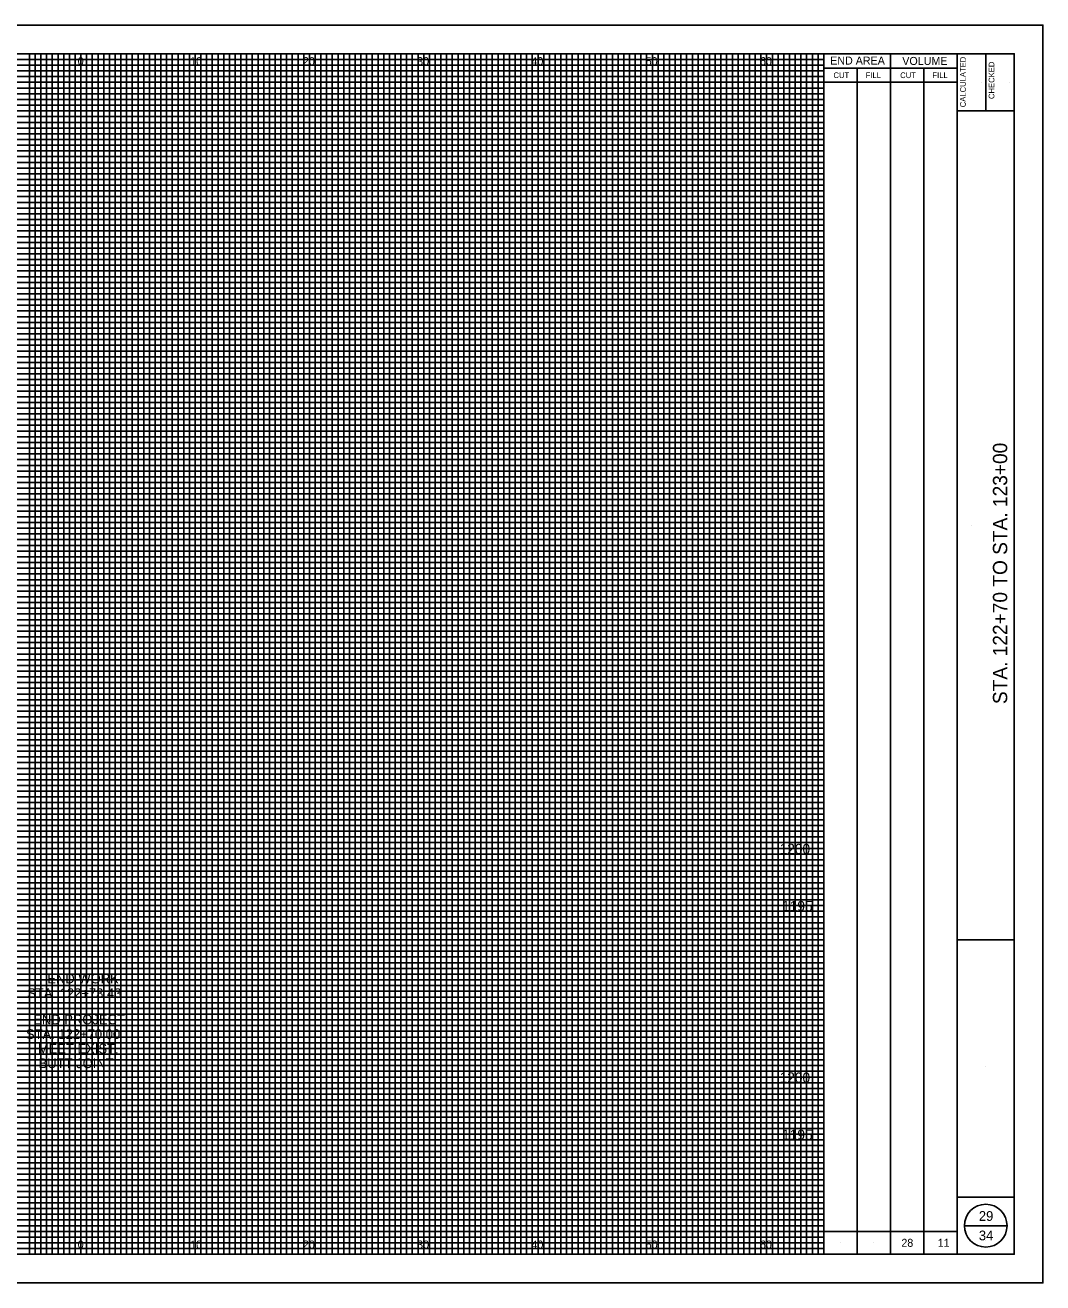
# Model space of a CAD drawing. Extents: x -10 to 160, y -13 to 1488.
# Drawn here: x 71 to 160, y 1377.5 to 1487.5 of the extents above; entities that cross this region are included whole.
import ezdxf

# ---------------------------------------------------------------- set-up
doc = ezdxf.new("R2010")
doc.units = 0
for name, color, linetype in [('DR_X_Storm_Sewer', 7, 'Continuous'), ('GK_Cells', 7, 'Continuous'), ('GK_Visualization', 7, 'Continuous'), ('PF_P_Sta_Elev_Text', 7, 'Continuous'), ('PF_X_Ground_Line', 7, 'Continuous'), ('PV_P_EOP', 7, 'Continuous'), ('PV_P_Shoulder', 7, 'Continuous')]:
    doc.layers.add(name, color=color, linetype=linetype)

msp = doc.modelspace()

# ---------------------------------------------------------------- linework, layer by layer
at = {"layer": 'GK_Cells'}
for p, q in [((152.5, 1380), (152.5, 1485)), ((155, 1485), (155, 1480)), ((152.5, 1480), (157.5, 1480)), ((152.5, 1407.5), (157.5, 1407.5)), ((152.5, 1385), (157.5, 1385))]:
    msp.add_line(p, q, dxfattribs=at)
msp.add_lwpolyline([(0, 1485), (157.5, 1485), (157.5, 1380), (0, 1380)], close=True, dxfattribs=at)
at = {"layer": 'PF_P_Sta_Elev_Text'}
msp.add_lwpolyline([(-10, 1377.5), (160, 1377.5), (160, 1487.5), (-10, 1487.5)], close=True, dxfattribs=at)
at = {"layer": 'PF_X_Ground_Line'}
for p, q in [((140.83, 1380), (140.83, 1485)), ((146.67, 1380), (146.67, 1485)), ((140.83, 1483.75), (152.5, 1483.75)), ((143.75, 1380), (143.75, 1483.75)), ((149.58, 1380), (149.58, 1483.75)), ((140.83, 1482.5), (152.5, 1482.5)), ((154.6, 1482.52), (154.6, 1482.52)), ((157.1, 1482.52), (157.1, 1482.52)), ((153.75, 1443.75), (153.75, 1443.75)), ((156.26, 1443.75), (156.26, 1443.75)), ((155, 1396.46), (155, 1396.46)), ((155, 1382.92), (155, 1382.92)), ((140.83, 1382), (152.5, 1382)), ((153.12, 1382.5), (156.88, 1382.5)), ((142.29, 1381), (142.29, 1381)), ((145.21, 1381), (145.21, 1381)), ((148.12, 1381), (148.12, 1381)), ((151.04, 1381), (151.04, 1381)), ((155, 1381.22), (155, 1381.22))]:
    msp.add_line(p, q, dxfattribs=at)
msp.add_circle((155, 1382.5), 1.87, dxfattribs=at)
at = {"layer": 'PV_P_EOP'}
for p, q in [((71.33, 1380), (71.33, 1485)), ((71.83, 1380), (71.83, 1485)), ((72.33, 1380), (72.33, 1485)), ((72.83, 1380), (72.83, 1485)), ((73.33, 1380), (73.33, 1485)), ((73.83, 1380), (73.83, 1485)), ((74.33, 1380), (74.33, 1485)), ((74.83, 1380), (74.83, 1485)), ((75.33, 1380), (75.33, 1485)), ((76.33, 1380), (76.33, 1485)), ((76.83, 1380), (76.83, 1485)), ((77.33, 1380), (77.33, 1485)), ((77.83, 1380), (77.83, 1485)), ((78.33, 1380), (78.33, 1485)), ((78.83, 1380), (78.83, 1485)), ((79.33, 1380), (79.33, 1485)), ((79.83, 1380), (79.83, 1485)), ((80.33, 1380), (80.33, 1485)), ((81.33, 1380), (81.33, 1485)), ((81.83, 1380), (81.83, 1485)), ((82.33, 1380), (82.33, 1485)), ((82.83, 1380), (82.83, 1485)), ((83.33, 1380), (83.33, 1485)), ((83.83, 1380), (83.83, 1485)), ((84.33, 1380), (84.33, 1485)), ((84.83, 1380), (84.83, 1485)), ((85.33, 1380), (85.33, 1485)), ((86.33, 1380), (86.33, 1485)), ((86.83, 1380), (86.83, 1485)), ((87.33, 1380), (87.33, 1485)), ((87.83, 1380), (87.83, 1485)), ((88.33, 1380), (88.33, 1485)), ((88.83, 1380), (88.83, 1485)), ((89.33, 1380), (89.33, 1485)), ((89.83, 1380), (89.83, 1485)), ((90.33, 1380), (90.33, 1485)), ((91.33, 1380), (91.33, 1485)), ((91.83, 1380), (91.83, 1485)), ((92.33, 1380), (92.33, 1485)), ((92.83, 1380), (92.83, 1485)), ((93.33, 1380), (93.33, 1485)), ((93.83, 1380), (93.83, 1485)), ((94.33, 1380), (94.33, 1485)), ((94.83, 1380), (94.83, 1485)), ((95.33, 1380), (95.33, 1485)), ((96.33, 1380), (96.33, 1485)), ((96.83, 1380), (96.83, 1485)), ((97.33, 1380), (97.33, 1485)), ((97.83, 1380), (97.83, 1485)), ((98.33, 1380), (98.33, 1485)), ((98.83, 1380), (98.83, 1485)), ((99.33, 1380), (99.33, 1485)), ((99.83, 1380), (99.83, 1485)), ((100.33, 1380), (100.33, 1485)), ((101.33, 1380), (101.33, 1485)), ((101.83, 1380), (101.83, 1485)), ((102.33, 1380), (102.33, 1485)), ((102.83, 1380), (102.83, 1485)), ((103.33, 1380), (103.33, 1485)), ((103.83, 1380), (103.83, 1485)), ((104.33, 1380), (104.33, 1485)), ((104.83, 1380), (104.83, 1485)), ((105.33, 1380), (105.33, 1485)), ((106.33, 1380), (106.33, 1485)), ((106.83, 1380), (106.83, 1485)), ((107.33, 1380), (107.33, 1485)), ((107.83, 1380), (107.83, 1485)), ((108.33, 1380), (108.33, 1485)), ((108.83, 1380), (108.83, 1485)), ((109.33, 1380), (109.33, 1485)), ((109.83, 1380), (109.83, 1485)), ((110.33, 1380), (110.33, 1485)), ((111.33, 1380), (111.33, 1485)), ((111.83, 1380), (111.83, 1485)), ((112.33, 1380), (112.33, 1485)), ((112.83, 1380), (112.83, 1485)), ((113.33, 1380), (113.33, 1485)), ((113.83, 1380), (113.83, 1485)), ((114.33, 1380), (114.33, 1485)), ((114.83, 1380), (114.83, 1485)), ((115.33, 1380), (115.33, 1485)), ((116.33, 1380), (116.33, 1485)), ((116.83, 1380), (116.83, 1485)), ((117.33, 1380), (117.33, 1485)), ((117.83, 1380), (117.83, 1485)), ((118.33, 1380), (118.33, 1485)), ((118.83, 1380), (118.83, 1485)), ((119.33, 1380), (119.33, 1485)), ((119.83, 1380), (119.83, 1485)), ((120.33, 1380), (120.33, 1485)), ((121.33, 1380), (121.33, 1485)), ((121.83, 1380), (121.83, 1485)), ((122.33, 1380), (122.33, 1485)), ((122.83, 1380), (122.83, 1485)), ((123.33, 1380), (123.33, 1485)), ((123.83, 1380), (123.83, 1485)), ((124.33, 1380), (124.33, 1485)), ((124.83, 1380), (124.83, 1485)), ((125.33, 1380), (125.33, 1485)), ((126.33, 1380), (126.33, 1485)), ((126.83, 1380), (126.83, 1485)), ((127.33, 1380), (127.33, 1485)), ((127.83, 1380), (127.83, 1485)), ((128.33, 1380), (128.33, 1485)), ((128.83, 1380), (128.83, 1485)), ((129.33, 1380), (129.33, 1485)), ((129.83, 1380), (129.83, 1485)), ((130.33, 1380), (130.33, 1485)), ((131.33, 1380), (131.33, 1485)), ((131.83, 1380), (131.83, 1485)), ((132.33, 1380), (132.33, 1485)), ((132.83, 1380), (132.83, 1485)), ((133.33, 1380), (133.33, 1485)), ((133.83, 1380), (133.83, 1485)), ((134.33, 1380), (134.33, 1485)), ((134.83, 1380), (134.83, 1485)), ((135.33, 1380), (135.33, 1485)), ((136.33, 1380), (136.33, 1485)), ((136.83, 1380), (136.83, 1485)), ((137.33, 1380), (137.33, 1485)), ((137.83, 1380), (137.83, 1485)), ((138.33, 1380), (138.33, 1485)), ((138.83, 1380), (138.83, 1485)), ((139.33, 1380), (139.33, 1485)), ((139.83, 1380), (139.83, 1485)), ((140.33, 1380), (140.33, 1485)), ((5.83, 1484.5), (140.83, 1484.5)), ((5.83, 1484), (140.83, 1484)), ((5.83, 1483.5), (140.83, 1483.5)), ((5.83, 1483), (140.83, 1483)), ((5.83, 1482.5), (140.83, 1482.5)), ((5.83, 1482), (140.83, 1482)), ((5.83, 1481.5), (140.83, 1481.5)), ((5.83, 1481), (140.83, 1481)), ((5.83, 1480.5), (140.83, 1480.5)), ((5.83, 1479.5), (140.83, 1479.5)), ((5.83, 1479), (140.83, 1479)), ((5.83, 1478.5), (140.83, 1478.5)), ((5.83, 1478), (140.83, 1478)), ((5.83, 1477.5), (140.83, 1477.5)), ((5.83, 1477), (140.83, 1477)), ((5.83, 1476.5), (140.83, 1476.5)), ((5.83, 1476), (140.83, 1476)), ((5.83, 1475.5), (140.83, 1475.5)), ((5.83, 1474.5), (140.83, 1474.5)), ((5.83, 1474), (140.83, 1474)), ((5.83, 1473.5), (140.83, 1473.5)), ((5.83, 1473), (140.83, 1473)), ((5.83, 1472.5), (140.83, 1472.5)), ((5.83, 1472), (140.83, 1472)), ((5.83, 1471.5), (140.83, 1471.5)), ((5.83, 1471), (140.83, 1471)), ((5.83, 1470.5), (140.83, 1470.5)), ((5.83, 1469.5), (140.83, 1469.5)), ((5.83, 1469), (140.83, 1469)), ((5.83, 1468.5), (140.83, 1468.5)), ((5.83, 1468), (140.83, 1468)), ((5.83, 1467.5), (140.83, 1467.5)), ((5.83, 1467), (140.83, 1467)), ((5.83, 1466.5), (140.83, 1466.5)), ((5.83, 1466), (140.83, 1466)), ((5.83, 1465.5), (140.83, 1465.5)), ((5.83, 1464.5), (140.83, 1464.5)), ((5.83, 1464), (140.83, 1464)), ((5.83, 1463.5), (140.83, 1463.5)), ((5.83, 1463), (140.83, 1463)), ((5.83, 1462.5), (140.83, 1462.5)), ((5.83, 1462), (140.83, 1462)), ((5.83, 1461.5), (140.83, 1461.5)), ((5.83, 1461), (140.83, 1461)), ((5.83, 1460.5), (140.83, 1460.5)), ((5.83, 1459.5), (140.83, 1459.5)), ((5.83, 1459), (140.83, 1459)), ((5.83, 1458.5), (140.83, 1458.5)), ((5.83, 1458), (140.83, 1458)), ((5.83, 1457.5), (140.83, 1457.5)), ((5.83, 1457), (140.83, 1457)), ((5.83, 1456.5), (140.83, 1456.5)), ((5.83, 1456), (140.83, 1456)), ((5.83, 1455.5), (140.83, 1455.5)), ((5.83, 1454.5), (140.83, 1454.5)), ((5.83, 1454), (140.83, 1454)), ((5.83, 1453.5), (140.83, 1453.5)), ((5.83, 1453), (140.83, 1453)), ((5.83, 1452.5), (140.83, 1452.5)), ((5.83, 1452), (140.83, 1452)), ((5.83, 1451.5), (140.83, 1451.5)), ((5.83, 1451), (140.83, 1451)), ((5.83, 1450.5), (140.83, 1450.5)), ((5.83, 1449.5), (140.83, 1449.5)), ((5.83, 1449), (140.83, 1449)), ((5.83, 1448.5), (140.83, 1448.5)), ((5.83, 1448), (140.83, 1448)), ((5.83, 1447.5), (140.83, 1447.5)), ((5.83, 1447), (140.83, 1447)), ((5.83, 1446.5), (140.83, 1446.5)), ((5.83, 1446), (140.83, 1446)), ((5.83, 1445.5), (140.83, 1445.5)), ((5.83, 1444.5), (140.83, 1444.5)), ((5.83, 1444), (140.83, 1444)), ((5.83, 1443.5), (140.83, 1443.5)), ((5.83, 1443), (140.83, 1443)), ((5.83, 1442.5), (140.83, 1442.5)), ((5.83, 1442), (140.83, 1442)), ((5.83, 1441.5), (140.83, 1441.5)), ((5.83, 1441), (140.83, 1441)), ((5.83, 1440.5), (140.83, 1440.5)), ((5.83, 1439.5), (140.83, 1439.5)), ((5.83, 1439), (140.83, 1439)), ((5.83, 1438.5), (140.83, 1438.5)), ((5.83, 1438), (140.83, 1438)), ((5.83, 1437.5), (140.83, 1437.5)), ((5.83, 1437), (140.83, 1437)), ((5.83, 1436.5), (140.83, 1436.5)), ((5.83, 1436), (140.83, 1436)), ((5.83, 1435.5), (140.83, 1435.5)), ((5.83, 1434.5), (140.83, 1434.5)), ((5.83, 1434), (140.83, 1434)), ((5.83, 1433.5), (140.83, 1433.5)), ((5.83, 1433), (140.83, 1433)), ((5.83, 1432.5), (140.83, 1432.5)), ((5.83, 1432), (140.83, 1432)), ((5.83, 1431.5), (140.83, 1431.5)), ((5.83, 1431), (140.83, 1431)), ((5.83, 1430.5), (140.83, 1430.5)), ((5.83, 1429.5), (140.83, 1429.5)), ((5.83, 1429), (140.83, 1429)), ((5.83, 1428.5), (140.83, 1428.5)), ((5.83, 1428), (140.83, 1428)), ((5.83, 1427.5), (140.83, 1427.5)), ((5.83, 1427), (140.83, 1427)), ((5.83, 1426.5), (140.83, 1426.5)), ((5.83, 1426), (140.83, 1426)), ((5.83, 1425.5), (140.83, 1425.5)), ((5.83, 1424.5), (140.83, 1424.5)), ((5.83, 1424), (140.83, 1424)), ((5.83, 1423.5), (140.83, 1423.5)), ((5.83, 1423), (140.83, 1423)), ((5.83, 1422.5), (140.83, 1422.5)), ((5.83, 1422), (140.83, 1422)), ((5.83, 1421.5), (140.83, 1421.5)), ((5.83, 1421), (140.83, 1421)), ((5.83, 1420.5), (140.83, 1420.5)), ((5.83, 1419.5), (140.83, 1419.5)), ((5.83, 1419), (140.83, 1419)), ((5.83, 1418.5), (140.83, 1418.5)), ((5.83, 1418), (140.83, 1418)), ((5.83, 1417.5), (140.83, 1417.5)), ((5.83, 1417), (140.83, 1417)), ((5.83, 1416.5), (140.83, 1416.5)), ((5.83, 1416), (140.83, 1416)), ((5.83, 1415.5), (140.83, 1415.5)), ((5.83, 1414.5), (140.83, 1414.5)), ((5.83, 1414), (140.83, 1414)), ((5.83, 1413.5), (140.83, 1413.5)), ((5.83, 1413), (140.83, 1413)), ((5.83, 1412.5), (140.83, 1412.5)), ((5.83, 1412), (140.83, 1412)), ((5.83, 1411.5), (140.83, 1411.5)), ((5.83, 1411), (140.83, 1411)), ((5.83, 1410.5), (140.83, 1410.5)), ((5.83, 1409.5), (140.83, 1409.5)), ((5.83, 1409), (140.83, 1409)), ((5.83, 1408.5), (140.83, 1408.5)), ((5.83, 1408), (140.83, 1408)), ((5.83, 1407.5), (140.83, 1407.5)), ((5.83, 1407), (140.83, 1407)), ((5.83, 1406.5), (140.83, 1406.5)), ((5.83, 1406), (140.83, 1406)), ((5.83, 1405.5), (140.83, 1405.5)), ((5.83, 1404.5), (140.83, 1404.5)), ((5.83, 1404), (140.83, 1404)), ((5.83, 1403.5), (140.83, 1403.5)), ((5.83, 1403), (140.83, 1403)), ((5.83, 1402.5), (140.83, 1402.5)), ((5.83, 1402), (140.83, 1402)), ((5.83, 1401.5), (140.83, 1401.5)), ((5.83, 1401), (140.83, 1401)), ((5.83, 1400.5), (140.83, 1400.5)), ((5.83, 1399.5), (140.83, 1399.5)), ((5.83, 1399), (140.83, 1399)), ((5.83, 1398.5), (140.83, 1398.5)), ((5.83, 1398), (140.83, 1398)), ((5.83, 1397.5), (140.83, 1397.5)), ((5.83, 1397), (140.83, 1397)), ((5.83, 1396.5), (140.83, 1396.5)), ((5.83, 1396), (140.83, 1396)), ((5.83, 1395.5), (140.83, 1395.5)), ((5.83, 1394.5), (140.83, 1394.5)), ((5.83, 1394), (140.83, 1394)), ((5.83, 1393.5), (140.83, 1393.5)), ((5.83, 1393), (140.83, 1393)), ((5.83, 1392.5), (140.83, 1392.5)), ((5.83, 1392), (140.83, 1392)), ((5.83, 1391.5), (140.83, 1391.5)), ((5.83, 1391), (140.83, 1391)), ((5.83, 1390.5), (140.83, 1390.5)), ((5.83, 1389.5), (140.83, 1389.5)), ((5.83, 1389), (140.83, 1389)), ((5.83, 1388.5), (140.83, 1388.5)), ((5.83, 1388), (140.83, 1388)), ((5.83, 1387.5), (140.83, 1387.5)), ((5.83, 1387), (140.83, 1387)), ((5.83, 1386.5), (140.83, 1386.5)), ((5.83, 1386), (140.83, 1386)), ((5.83, 1385.5), (140.83, 1385.5)), ((5.83, 1384.5), (140.83, 1384.5)), ((5.83, 1384), (140.83, 1384)), ((5.83, 1383.5), (140.83, 1383.5)), ((5.83, 1383), (140.83, 1383)), ((5.83, 1382.5), (140.83, 1382.5)), ((5.83, 1382), (140.83, 1382)), ((5.83, 1381.5), (140.83, 1381.5)), ((5.83, 1381), (140.83, 1381)), ((5.83, 1380.5), (140.83, 1380.5))]:
    msp.add_line(p, q, dxfattribs=at)
at = {"layer": 'PV_P_Shoulder'}
for p, q in [((75.83, 1380), (75.83, 1485)), ((80.83, 1380), (80.83, 1485)), ((85.83, 1380), (85.83, 1485)), ((90.83, 1380), (90.83, 1485)), ((95.83, 1380), (95.83, 1485)), ((100.83, 1380), (100.83, 1485)), ((105.83, 1380), (105.83, 1485)), ((110.83, 1380), (110.83, 1485)), ((115.83, 1380), (115.83, 1485)), ((120.83, 1380), (120.83, 1485)), ((125.83, 1380), (125.83, 1485)), ((130.83, 1380), (130.83, 1485)), ((135.83, 1380), (135.83, 1485)), ((11.66, 1480), (140.83, 1480)), ((11.66, 1475), (140.83, 1475)), ((11.66, 1470), (140.83, 1470)), ((11.66, 1465), (140.83, 1465)), ((11.66, 1460), (140.83, 1460)), ((11.66, 1455), (140.83, 1455)), ((11.66, 1450), (140.83, 1450)), ((11.66, 1445), (140.83, 1445)), ((11.66, 1440), (140.83, 1440)), ((11.66, 1435), (140.83, 1435)), ((11.66, 1430), (140.83, 1430)), ((11.66, 1425), (140.83, 1425)), ((11.66, 1420), (140.83, 1420)), ((11.66, 1415), (140.83, 1415)), ((11.66, 1410), (140.83, 1410)), ((11.66, 1405), (140.83, 1405)), ((11.66, 1400), (140.83, 1400)), ((11.66, 1395), (140.83, 1395)), ((11.66, 1390), (140.83, 1390)), ((11.66, 1385), (140.83, 1385))]:
    msp.add_line(p, q, dxfattribs=at)

# ---------------------------------------------------------------- texts
at = {"layer": 'DR_X_Storm_Sewer'}
for s, height, p in [('0', 0.7, (75.55, 1484)), ('0', 0.7, (75.55, 1484)), ('10', 0.7, (85.39, 1484)), ('20', 0.7, (95.26, 1484)), ('30', 0.7, (105.25, 1484)), ('40', 0.7, (115.25, 1484)), ('50', 0.7, (125.25, 1484)), ('60', 0.7, (135.25, 1484)), ('1200', 0.9, (136.96, 1415)), ('1195', 0.9, (137.18, 1410)), ('1200', 0.9, (136.96, 1395)), ('1195', 0.9, (137.18, 1390)), ('29', 0.85, (154.4, 1382.92)), ('34', 0.85, (154.4, 1381.22)), ('0', 0.7, (75.55, 1380.5)), ('0', 0.7, (75.55, 1380.5)), ('10', 0.7, (85.39, 1380.5)), ('20', 0.7, (95.26, 1380.5)), ('30', 0.7, (105.25, 1380.5)), ('40', 0.7, (115.25, 1380.5)), ('50', 0.7, (125.25, 1380.5)), ('60', 0.7, (135.25, 1380.5)), ('28', 0.7, (147.62, 1380.65)), ('11', 0.7, (150.8, 1380.65))]:
    msp.add_text(s, height=height, dxfattribs=at).set_placement(p)
at = {"layer": 'GK_Visualization'}
for s, p in [('END WORK', (72.89, 1403.69)), ('STA. 122+73.43', (71.13, 1402.41)), ('END PROJECT', (71.66, 1400.11)), ('STA. 122+70.00', (71.02, 1398.83)), ('MEET EXIST.', (72.06, 1397.56)), ('BUTT JOINT', (72.13, 1396.28))]:
    msp.add_text(s, height=0.85, dxfattribs=at).set_placement(p)
at = {"layer": 'PF_X_Ground_Line'}
for s, height, p in [('END AREA', 0.7, (141.39, 1484.05)), ('VOLUME', 0.7, (147.7, 1484.02)), ('CUT', 0.5, (141.68, 1482.87)), ('FILL', 0.5, (144.5, 1482.87)), ('CUT', 0.5, (147.52, 1482.87)), ('FILL', 0.5, (150.34, 1482.87))]:
    msp.add_text(s, height=height, dxfattribs=at).set_placement(p)
for s, height, p in [('CALCULATED', 0.5, (153.26, 1480.32)), ('CHECKED', 0.5, (155.76, 1481.04)), ('STA. 122+70 TO STA. 123+00', 1.25, (156.88, 1428.12))]:
    msp.add_text(s, height=height, rotation=90, dxfattribs=at).set_placement(p)

doc.saveas('drawing.dxf')
